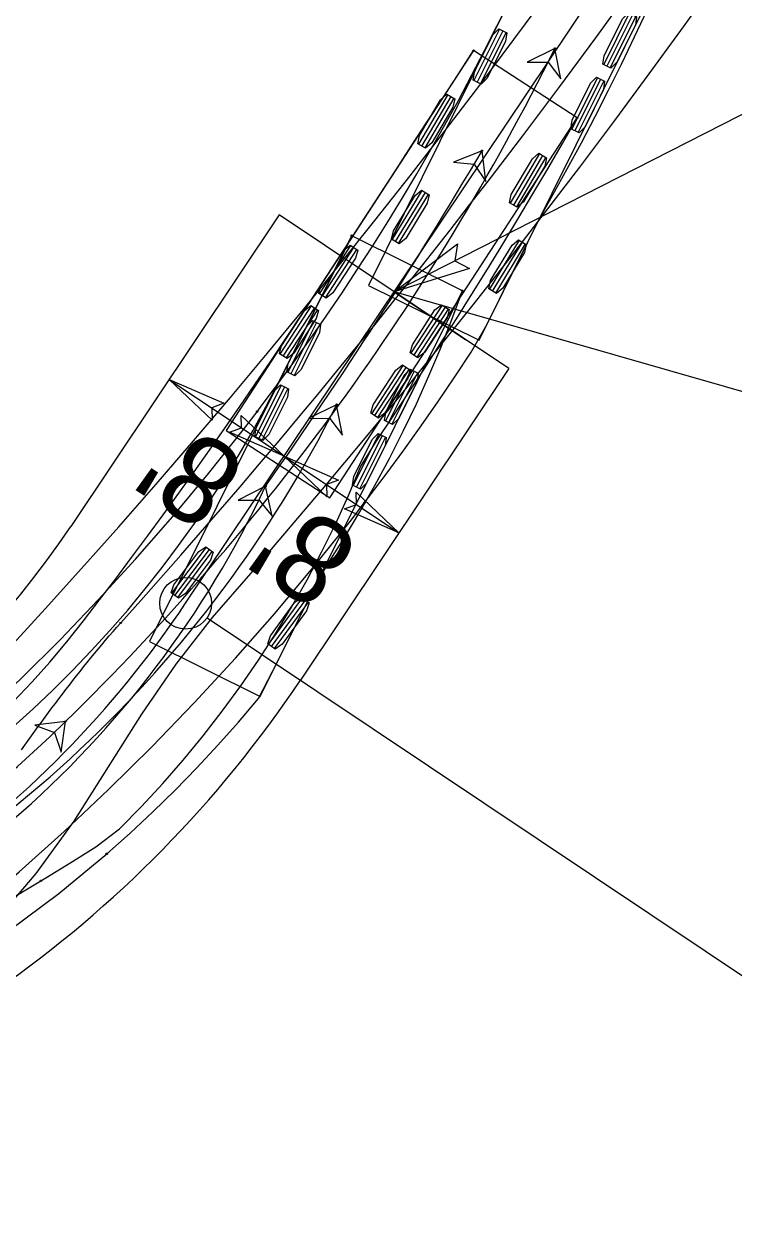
# Model space of a CAD drawing. Extents: x 1735795 to 1737428, y 699740 to 701024.
# Drawn here: x 1736310 to 1736351.1, y 700331.3 to 700401.5 of the extents above; entities that cross this region are included whole.
import ezdxf

# ---------------------------------------------------------------- set-up
doc = ezdxf.new("R2010")
doc.units = 0
for name, color, linetype in [('Prop Dimension', 7, 'Continuous'), ('Prop Dimension Text', 7, 'Continuous'), ('Prop EOT', 7, 'Continuous'), ('Prop Horizontal Alignment', 7, 'Continuous'), ('Prop Horizontal Alignment Station Label', 7, 'Continuous'), ('Prop Horizontal Alignment Tick Small', 7, 'Continuous'), ('Prop Terminator CELL', 7, 'Continuous'), ('Scratch_Level_4', 7, 'Continuous'), ('Scratch_Level_5', 7, 'Continuous'), ('Scratch_Level_6', 7, 'Continuous'), ('Scratch_Level_7', 7, 'Continuous')]:
    doc.layers.add(name, color=color, linetype=linetype)

msp = doc.modelspace()

# ---------------------------------------------------------------- linework, layer by layer
at = {"layer": 'Prop Dimension'}
msp.add_line((1736318.442, 700380.927), (1736331.741, 700372.031), dxfattribs=at)
msp.add_lwpolyline([(1736375.152, 700400.171), (1736373.427, 700407.411), (1736331.462, 700386.001)], dxfattribs=at)
at = {"layer": 'Prop EOT'}
for p, q in [((1736324.812, 700390.449), (1736312.743, 700372.408)), ((1736338.111, 700381.553), (1736324.812, 700390.449)), ((1736338.111, 700381.553), (1736326.042, 700363.511))]:
    msp.add_line(p, q, dxfattribs=at)
for radius in [52, 68]:
    msp.add_arc((1736269.522, 700401.32), radius, 283.65186, 326.21936, dxfattribs=at)
at = {"layer": 'Prop Horizontal Alignment'}
msp.add_line((1736319.393, 700367.959), (1736380.982, 700460.028), dxfattribs=at)
msp.add_arc((1736269.522, 700401.32), 60, 283.65186, 326.21936, dxfattribs=at)
at = {"layer": 'Prop Horizontal Alignment Station Label'}
msp.add_line((1736320.639, 700367.125), (1736374.148, 700331.331), dxfattribs=at)
msp.add_lwpolyline([(1736353.768, 700379.602), (1736331.462, 700386.001)], dxfattribs=at)
msp.add_circle((1736319.393, 700367.959), 1.5, dxfattribs=at)
at = {"layer": 'Prop Horizontal Alignment Tick Small'}
msp.add_line((1736331.462, 700386.001), (1736335.617, 700383.221), dxfattribs=at)
at = {"layer": 'Prop Terminator CELL'}
for points in [[(1736335.822, 700387.356), (1736331.462, 700386.001), (1736335.129, 700388.77), (1736334.98, 700387.796)], [(1736320.924, 700378.567), (1736318.442, 700380.927), (1736321.597, 700379.539), (1736320.905, 700379.28)], [(1736322.61, 700378.839), (1736325.092, 700376.479), (1736321.937, 700377.867), (1736322.629, 700378.126)], [(1736327.574, 700374.119), (1736325.092, 700376.479), (1736328.246, 700375.091), (1736327.554, 700374.832)], [(1736329.259, 700374.39), (1736331.741, 700372.031), (1736328.587, 700373.419), (1736329.279, 700373.678)]]:
    msp.add_lwpolyline(points, close=True, dxfattribs=at)
at = {"layer": 'Scratch_Level_4'}
for points in [[(1736308.306, 700349.473), (1736310.743, 700352.311), (1736312.941, 700355.337), (1736314.922, 700358.483), (1736316.864, 700361.535), (1736318.855, 700364.437), (1736320.956, 700367.144), (1736323.163, 700369.691), (1736325.358, 700372.244), (1736327.534, 700374.813), (1736329.691, 700377.396), (1736331.828, 700379.995), (1736333.946, 700382.61), (1736336.044, 700385.239), (1736338.122, 700387.884), (1736340.181, 700390.545), (1736342.219, 700393.22), (1736344.238, 700395.91), (1736346.236, 700398.616), (1736348.214, 700401.336), (1736350.171, 700404.071)], [(1736309.218, 700365.406), (1736311.264, 700367.635), (1736313.369, 700369.964), (1736315.521, 700372.381), (1736317.695, 700374.862), (1736319.852, 700377.363), (1736321.99, 700379.881), (1736324.11, 700382.417), (1736326.21, 700384.968), (1736328.291, 700387.537), (1736330.352, 700390.121), (1736332.395, 700392.72), (1736334.417, 700395.336), (1736336.42, 700397.966), (1736338.403, 700400.612), (1736340.366, 700403.273)], [(1736309.881, 700359.478), (1736310.077, 700359.748), (1736310.272, 700360.018), (1736310.469, 700360.288), (1736310.665, 700360.557), (1736310.862, 700360.826), (1736311.06, 700361.094), (1736311.258, 700361.362), (1736311.457, 700361.63), (1736311.656, 700361.897), (1736311.856, 700362.164), (1736312.057, 700362.43), (1736312.258, 700362.695), (1736312.461, 700362.96), (1736312.664, 700363.224), (1736312.869, 700363.487), (1736313.074, 700363.75), (1736313.28, 700364.012), (1736313.488, 700364.273), (1736313.697, 700364.533), (1736313.906, 700364.792), (1736314.117, 700365.05), (1736314.33, 700365.306), (1736314.543, 700365.562), (1736314.758, 700365.817), (1736314.975, 700366.071), (1736315.193, 700366.323), (1736315.412, 700366.574), (1736315.633, 700366.823)]]:
    msp.add_lwpolyline(points, dxfattribs=at)
msp.add_circle((1736315.633, 700366.823), 0.0417, dxfattribs=at)
msp.add_circle((1736315.633, 700366.823), 0.0417, dxfattribs=at)
msp.add_arc((1735985.328, 700663.125), 443.73, 318.10624, 332.53243, dxfattribs=at)
at = {"layer": 'Scratch_Level_5'}
for p, q in [((1736341.635, 700409.878), (1736329.974, 700386.364)), ((1736336.381, 700383.187), (1736348.043, 700406.7)), ((1736345.082, 700402.137), (1736343.601, 700399.151)), ((1736345.269, 700402.045), (1736343.788, 700399.058)), ((1736345.455, 700401.952), (1736343.974, 700398.966)), ((1736337.57, 700401.212), (1736336.089, 700398.226)), ((1736337.756, 700401.119), (1736336.275, 700398.133)), ((1736337.943, 700401.027), (1736336.462, 700398.04)), ((1736343.231, 700398.404), (1736341.75, 700395.418)), ((1736343.417, 700398.312), (1736341.936, 700395.326)), ((1736343.604, 700398.219), (1736342.123, 700395.233)), ((1736331.359, 700389.013), (1736333.097, 700391.857)), ((1736331.536, 700388.904), (1736333.275, 700391.748)), ((1736331.714, 700388.796), (1736333.453, 700391.64)), ((1736336.989, 700386.139), (1736338.718, 700388.989)), ((1736337.167, 700386.031), (1736338.896, 700388.881)), ((1736337.345, 700385.923), (1736339.074, 700388.772)), ((1736329.974, 700386.364), (1736336.381, 700383.187)), ((1736336.381, 700383.187), (1736336.381, 700383.187))]:
    msp.add_line(p, q, dxfattribs=at)
for points in [[(1736323.53, 700379.053), (1736323.726, 700379.312), (1736324.702, 700380.616), (1736325.662, 700381.931), (1736326.606, 700383.257), (1736327.536, 700384.594), (1736328.449, 700385.942), (1736329.347, 700387.3), (1736330.229, 700388.668), (1736331.096, 700390.047), (1736331.946, 700391.435), (1736332.78, 700392.834), (1736333.598, 700394.241), (1736334.399, 700395.659), (1736335.184, 700397.085), (1736335.952, 700398.521), (1736336.704, 700399.965), (1736337.439, 700401.418), (1736338.163, 700402.876), (1736338.886, 700404.335), (1736339.609, 700405.794), (1736340.333, 700407.252), (1736341.056, 700408.711), (1736341.635, 700409.878)], [(1736329.755, 700373.795), (1736329.964, 700374.069), (1736331, 700375.445), (1736332.019, 700376.834), (1736333.023, 700378.234), (1736334.01, 700379.645), (1736334.98, 700381.068), (1736335.935, 700382.503), (1736336.781, 700383.992), (1736337.541, 700385.525), (1736338.301, 700387.058), (1736339.061, 700388.591), (1736339.822, 700390.124), (1736340.659, 700391.619), (1736341.491, 700393.118), (1736342.305, 700394.627), (1736343.101, 700396.145), (1736343.88, 700397.672), (1736344.641, 700399.209), (1736345.384, 700400.754), (1736346.109, 700402.307), (1736346.816, 700403.869), (1736347.505, 700405.439), (1736348.043, 700406.7)], [(1736288.667, 700349.034), (1736288.956, 700349.168), (1736291.82, 700350.573), (1736294.622, 700352.098), (1736297.358, 700353.74), (1736300.021, 700355.496), (1736302.609, 700357.363), (1736305.115, 700359.337), (1736307.535, 700361.415), (1736309.866, 700363.594), (1736312.123, 700365.849), (1736314.329, 700368.154), (1736316.486, 700370.514), (1736318.627, 700372.967), (1736320.711, 700375.47), (1736322.736, 700378.02), (1736323.53, 700379.053)], [(1736291.733, 700340.652), (1736292.058, 700340.799), (1736295.273, 700342.343), (1736298.419, 700344.021), (1736301.492, 700345.83), (1736304.359, 700347.892), (1736307.082, 700350.115), (1736309.751, 700352.402), (1736312.367, 700354.752), (1736314.93, 700357.167), (1736317.438, 700359.646), (1736319.89, 700362.187), (1736322.278, 700364.782), (1736324.551, 700367.371), (1736326.763, 700370.013), (1736328.913, 700372.704), (1736329.755, 700373.795)]]:
    msp.add_lwpolyline(points, dxfattribs=at)
for points in [[(1736345.036, 700402.16), (1736345.501, 700401.929), (1736345.435, 700401.441), (1736344.368, 700399.291), (1736344.02, 700398.943), (1736343.555, 700399.174), (1736343.622, 700399.662), (1736344.688, 700401.812)], [(1736337.523, 700401.235), (1736337.989, 700401.004), (1736337.922, 700400.516), (1736336.856, 700398.366), (1736336.508, 700398.018), (1736336.042, 700398.249), (1736336.109, 700398.736), (1736337.176, 700400.886)], [(1736340.772, 700400.089), (1736339.167, 700399.302), (1736340.375, 700399.288), (1736341.117, 700398.334)], [(1736343.184, 700398.427), (1736343.65, 700398.196), (1736343.583, 700397.709), (1736342.517, 700395.559), (1736342.169, 700395.21), (1736341.703, 700395.441), (1736341.77, 700395.929), (1736342.837, 700398.079)], [(1736331.758, 700388.769), (1736331.314, 700389.04), (1736331.424, 700389.52), (1736332.676, 700391.567), (1736333.053, 700391.884), (1736333.497, 700391.613), (1736333.387, 700391.133), (1736332.135, 700389.085)], [(1736337.389, 700385.896), (1736336.945, 700386.166), (1736337.053, 700386.646), (1736338.298, 700388.698), (1736338.674, 700389.015), (1736339.119, 700388.746), (1736339.01, 700388.265), (1736337.765, 700386.214)], [(1736312.437, 700361.107), (1736310.662, 700360.893), (1736311.798, 700360.482), (1736312.184, 700359.337)]]:
    msp.add_lwpolyline(points, close=True, dxfattribs=at)
for centre in [(1736340.772, 700400.089), (1736323.53, 700379.053), (1736323.53, 700379.053), (1736329.755, 700373.795), (1736329.755, 700373.795), (1736312.437, 700361.107), (1736312.437, 700361.107)]:
    msp.add_circle(centre, 0.0417, dxfattribs=at)
for centre, radius, start, end in [((1736211.779, 700464.061), 143.985, 314.35399, 333.62156), ((1736257.104, 700417.702), 79.15, 285.0858, 314.35399)]:
    msp.add_arc(centre, radius, start, end, dxfattribs=at)
at = {"layer": 'Scratch_Level_6'}
for p, q in [((1736336.068, 700399.968), (1736321.749, 700377.971)), ((1736342.062, 700396.066), (1736336.068, 700399.968)), ((1736336.068, 700399.968), (1736336.068, 700399.968)), ((1736334.568, 700397.417), (1736332.876, 700394.545)), ((1736334.748, 700397.311), (1736333.055, 700394.439)), ((1736334.927, 700397.205), (1736333.235, 700394.334)), ((1736327.743, 700374.069), (1736342.062, 700396.066)), ((1736339.885, 700394), (1736338.19, 700391.13)), ((1736340.064, 700393.894), (1736338.369, 700391.024)), ((1736340.244, 700393.788), (1736338.549, 700390.918)), ((1736327.145, 700385.878), (1736328.963, 700388.672)), ((1736327.319, 700385.764), (1736329.138, 700388.558)), ((1736327.494, 700385.651), (1736329.312, 700388.444)), ((1736324.872, 700382.386), (1736326.69, 700385.18)), ((1736332.44, 700382.431), (1736334.259, 700385.224)), ((1736325.046, 700382.272), (1736326.865, 700385.066)), ((1736325.221, 700382.159), (1736327.039, 700384.952)), ((1736332.615, 700382.317), (1736334.434, 700385.111)), ((1736332.79, 700382.203), (1736334.608, 700384.997)), ((1736330.167, 700378.939), (1736331.986, 700381.732)), ((1736330.342, 700378.825), (1736332.16, 700381.619)), ((1736330.517, 700378.711), (1736332.335, 700381.505)), ((1736321.749, 700377.971), (1736327.743, 700374.069))]:
    msp.add_line(p, q, dxfattribs=at)
for points in [[(1736309.407, 700362.244), (1736310.508, 700363.407), (1736311.532, 700364.554), (1736312.522, 700365.731), (1736313.478, 700366.935), (1736314.414, 700368.155), (1736315.343, 700369.38), (1736316.266, 700370.61), (1736317.182, 700371.845), (1736318.091, 700373.085), (1736318.993, 700374.33), (1736319.889, 700375.579), (1736320.778, 700376.834), (1736321.661, 700378.093), (1736322.536, 700379.357), (1736323.405, 700380.626), (1736324.319, 700381.976), (1736325.237, 700383.35), (1736326.147, 700384.73), (1736327.05, 700386.115), (1736327.952, 700387.5), (1736328.854, 700388.885), (1736329.756, 700390.271), (1736330.657, 700391.656), (1736331.559, 700393.041), (1736332.461, 700394.427), (1736333.363, 700395.812), (1736334.265, 700397.197), (1736335.166, 700398.583), (1736336.068, 700399.968)], [(1736311.012, 700351.89), (1736311.302, 700352.065), (1736312.75, 700352.95), (1736314.191, 700353.845), (1736315.571, 700354.893), (1736316.838, 700356.187), (1736318.067, 700357.517), (1736319.257, 700358.881), (1736320.408, 700360.28), (1736321.518, 700361.712), (1736322.586, 700363.175), (1736323.611, 700364.669), (1736324.593, 700366.191), (1736325.53, 700367.742), (1736326.422, 700369.319), (1736327.269, 700370.921), (1736328.068, 700372.547), (1736328.821, 700374.196), (1736329.525, 700375.865), (1736330.423, 700377.325), (1736331.368, 700378.735), (1736332.306, 700380.15), (1736333.235, 700381.57), (1736334.155, 700382.996), (1736335.068, 700384.427), (1736335.972, 700385.864), (1736336.867, 700387.306), (1736337.754, 700388.753), (1736338.633, 700390.206), (1736339.503, 700391.663), (1736340.365, 700393.126), (1736341.218, 700394.593), (1736342.062, 700396.066)], [(1736291.015, 700341.184), (1736292.251, 700341.702), (1736295.003, 700342.985), (1736298.015, 700344.546), (1736301.034, 700346.111), (1736303.977, 700347.788), (1736306.924, 700349.469), (1736309.849, 700351.19), (1736311.012, 700351.89)]]:
    msp.add_lwpolyline(points, dxfattribs=at)
for points in [[(1736334.524, 700397.443), (1736334.972, 700397.179), (1736334.87, 700396.698), (1736333.651, 700394.63), (1736333.279, 700394.307), (1736332.831, 700394.571), (1736332.933, 700395.053), (1736334.152, 700397.121)], [(1736336.559, 700394.167), (1736334.901, 700393.499), (1736336.105, 700393.397), (1736336.776, 700392.393)], [(1736339.84, 700394.027), (1736340.288, 700393.762), (1736340.186, 700393.281), (1736338.965, 700391.214), (1736338.593, 700390.892), (1736338.145, 700391.156), (1736338.248, 700391.638), (1736339.468, 700393.704)], [(1736327.537, 700385.622), (1736327.101, 700385.906), (1736327.225, 700386.383), (1736328.534, 700388.394), (1736328.92, 700388.7), (1736329.356, 700388.416), (1736329.232, 700387.939), (1736327.923, 700385.928)], [(1736325.264, 700382.13), (1736324.828, 700382.414), (1736324.952, 700382.891), (1736326.261, 700384.902), (1736326.647, 700385.208), (1736327.083, 700384.924), (1736326.959, 700384.447), (1736325.65, 700382.436)], [(1736332.833, 700382.175), (1736332.397, 700382.459), (1736332.52, 700382.935), (1736333.83, 700384.947), (1736334.216, 700385.252), (1736334.651, 700384.969), (1736334.528, 700384.492), (1736333.219, 700382.481)], [(1736330.56, 700378.683), (1736330.124, 700378.967), (1736330.247, 700379.443), (1736331.557, 700381.455), (1736331.943, 700381.76), (1736332.378, 700381.477), (1736332.255, 700381), (1736330.946, 700378.989)], [(1736324.023, 700374.749), (1736322.436, 700373.926), (1736323.644, 700373.94), (1736324.407, 700373.003)]]:
    msp.add_lwpolyline(points, close=True, dxfattribs=at)
for centre in [(1736336.068, 700399.968), (1736342.062, 700396.066), (1736336.559, 700394.167), (1736324.023, 700374.749), (1736324.023, 700374.749), (1736311.012, 700351.89), (1736311.012, 700351.89)]:
    msp.add_circle(centre, 0.0417, dxfattribs=at)
for centre, radius, start, end in [((1736089.416, 700539.964), 286.943, 324.84609, 329.4625), ((1736271.357, 700399.418), 58.157, 310.74156, 334.90149)]:
    msp.add_arc(centre, radius, start, end, dxfattribs=at)
at = {"layer": 'Scratch_Level_7'}
for p, q in [((1736329.015, 700389.245), (1736317.309, 700365.754)), ((1736335.417, 700386.055), (1736329.015, 700389.245)), ((1736323.71, 700362.564), (1736335.417, 700386.055)), ((1736326.792, 700384.316), (1736325.305, 700381.333)), ((1736326.978, 700384.223), (1736325.491, 700381.24)), ((1736327.164, 700384.13), (1736325.678, 700381.147)), ((1736332.447, 700381.498), (1736330.96, 700378.514)), ((1736332.634, 700381.405), (1736331.147, 700378.422)), ((1736332.82, 700381.312), (1736331.333, 700378.329)), ((1736324.933, 700380.587), (1736323.446, 700377.604)), ((1736325.12, 700380.494), (1736323.633, 700377.511)), ((1736325.306, 700380.401), (1736323.819, 700377.418)), ((1736330.589, 700377.769), (1736329.102, 700374.785)), ((1736330.775, 700377.676), (1736329.288, 700374.692)), ((1736330.962, 700377.583), (1736329.475, 700374.599)), ((1736318.602, 700368.537), (1736320.605, 700371.201)), ((1736318.769, 700368.411), (1736320.771, 700371.076)), ((1736318.935, 700368.286), (1736320.938, 700370.951)), ((1736324.198, 700365.578), (1736326.164, 700368.269)), ((1736324.366, 700365.455), (1736326.333, 700368.146)), ((1736324.534, 700365.332), (1736326.501, 700368.023)), ((1736317.309, 700365.754), (1736323.71, 700362.564)), ((1736323.71, 700362.564), (1736323.71, 700362.564))]:
    msp.add_line(p, q, dxfattribs=at)
for points in [[(1736309.394, 700360.785), (1736310.567, 700361.849), (1736311.715, 700362.941), (1736312.836, 700364.059), (1736313.931, 700365.204), (1736314.999, 700366.374), (1736316.038, 700367.569), (1736317.049, 700368.789), (1736318.031, 700370.032), (1736318.983, 700371.298), (1736319.905, 700372.586), (1736320.796, 700373.895), (1736321.656, 700375.225), (1736322.484, 700376.576), (1736323.28, 700377.945), (1736324.044, 700379.333), (1736324.775, 700380.738), (1736325.482, 700382.155), (1736326.189, 700383.573), (1736326.895, 700384.991), (1736327.602, 700386.409), (1736328.308, 700387.827), (1736329.015, 700389.245)], [(1736314.831, 700353.454), (1736316.176, 700354.649), (1736317.493, 700355.875), (1736318.779, 700357.133), (1736320.036, 700358.42), (1736321.262, 700359.736), (1736322.457, 700361.081), (1736323.619, 700362.454), (1736324.43, 700364.008), (1736325.211, 700365.577), (1736325.993, 700367.145), (1736326.775, 700368.714), (1736327.629, 700370.246), (1736328.574, 700371.739), (1736329.482, 700373.254), (1736330.355, 700374.789), (1736331.191, 700376.345), (1736331.991, 700377.921), (1736332.752, 700379.514), (1736333.476, 700381.125), (1736334.162, 700382.753), (1736334.809, 700384.397), (1736335.417, 700386.055)], [(1736268.555, 700335.366), (1736271.506, 700335.45), (1736274.583, 700335.611), (1736277.666, 700335.921), (1736280.686, 700336.479), (1736283.654, 700337.168), (1736286.547, 700337.962), (1736289.827, 700339.014), (1736293.254, 700340.291), (1736296.618, 700341.734), (1736299.915, 700343.339), (1736303.135, 700345.104), (1736306.204, 700346.982), (1736309.181, 700349.002), (1736312.059, 700351.161), (1736314.831, 700353.454)]]:
    msp.add_lwpolyline(points, dxfattribs=at)
for points in [[(1736326.745, 700384.339), (1736327.211, 700384.107), (1736327.143, 700383.62), (1736326.072, 700381.472), (1736325.724, 700381.124), (1736325.259, 700381.356), (1736325.326, 700381.843), (1736326.397, 700383.991)], [(1736332.401, 700381.521), (1736332.866, 700381.289), (1736332.798, 700380.801), (1736331.728, 700378.653), (1736331.38, 700378.306), (1736330.914, 700378.537), (1736330.982, 700379.025), (1736332.052, 700381.173)], [(1736324.887, 700380.61), (1736325.352, 700380.378), (1736325.284, 700379.891), (1736324.214, 700377.742), (1736323.866, 700377.395), (1736323.4, 700377.627), (1736323.468, 700378.114), (1736324.539, 700380.262)], [(1736328.133, 700379.458), (1736326.526, 700378.674), (1736327.734, 700378.658), (1736328.475, 700377.703)], [(1736330.542, 700377.792), (1736331.008, 700377.56), (1736330.94, 700377.072), (1736329.869, 700374.924), (1736329.521, 700374.576), (1736329.056, 700374.808), (1736329.124, 700375.296), (1736330.194, 700377.444)], [(1736318.976, 700368.255), (1736318.561, 700368.568), (1736318.716, 700369.035), (1736320.158, 700370.953), (1736320.564, 700371.232), (1736320.979, 700370.92), (1736320.824, 700370.453), (1736319.382, 700368.534)], [(1736324.576, 700365.302), (1736324.156, 700365.609), (1736324.305, 700366.078), (1736325.721, 700368.015), (1736326.123, 700368.3), (1736326.543, 700367.993), (1736326.394, 700367.524), (1736324.977, 700365.586)]]:
    msp.add_lwpolyline(points, close=True, dxfattribs=at)
for centre in [(1736329.015, 700389.245), (1736335.417, 700386.055), (1736328.133, 700379.458), (1736314.831, 700353.454), (1736314.831, 700353.454)]:
    msp.add_circle(centre, 0.0417, dxfattribs=at)
msp.add_arc((1736264.962, 700410.938), 70.58, 292.87649, 333.51141, dxfattribs=at)

# ---------------------------------------------------------------- texts
at = {"layer": 'Prop Dimension Text'}
for p in [(1736323.127, 700376.16), (1736329.686, 700371.58)]:
    msp.add_text("8'", height=5, rotation=146.95015, dxfattribs=at).set_placement(p)

doc.saveas('drawing.dxf')
